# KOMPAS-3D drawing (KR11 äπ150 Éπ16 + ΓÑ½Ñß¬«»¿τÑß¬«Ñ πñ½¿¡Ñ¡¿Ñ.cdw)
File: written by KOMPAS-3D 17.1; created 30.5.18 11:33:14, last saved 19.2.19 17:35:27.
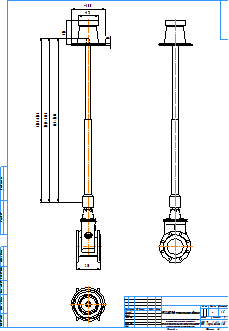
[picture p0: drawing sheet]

Sheet 1: A2, portrait

Title block, sheet 1: name: KR11 Ду150 Ру16 + телескопическое удлинение; sheets: 1; sheet format: A2; stored path: C:\Users\kka\KOMPAS_Work\!Trash\ГРАНАР KR Задвижки с приводами и удлинениями\С удлинениями\KR11 Ду150 Ру16 + телескопическое удлинение.cdw

Views: Вид 1, Проекционный вид 2, Проекционный вид 3
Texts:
  kka
  adl
  Рама для чертежей
  Лит-Масса-Масштаб
  Материал-Предприятие
  Масштаб
  Изм.
  Лист
  № докум.
  Подп.
  Дата
  Лит.
  Разраб.
  Пров.
  Т.контр.
  Листов
  Внимание! Данный продукт является объектом авторского права ООО «Торговый Дом АДЛ».
  Запрещается изменение, копирование, распространение
  (в том числе путем копирования на другие сайты и ресурсы в Интернете)
  или любое иное использование информации и объектов без предварительного
  согласия правообладателя (ООО «Торговый Дом АДЛ»).
  Н.контр.
  Утв.
  ООО "Торговый дом АДЛ"
  Изменение
  Номер документа
  Подпись
  Обозначение документа
  Наименование изделия
  Масса изделия по ГОСТ 2.109-73
  Порядковый номер листа
  Общее количество листов в документе
  Характер работы, выполненной лицом, подписавшим документ
  Наименование или индекс предприятия, выпускающего документ
  Инв. № подл.
  Подп. и дата
  Взам. инв. №
  Инв. № дубл.
  Инвентарный номер подлинника по ГОСТ 2.501-68
  Подпись принявшего подлинник в отдел технической документации
  Инвентарный номер подлинника, взамен которого выпущен данный подлинник
  Инвентарный номер дубликата по ГОСТ 2.502-68
  Подпись принявшего дубликат в отдел технической документации
  Справ. №
  Перв. примен.
  Обозначение документа, взамен или на основании которого выпущен данный документ
  Обозначение документа, в котором впервые записан данный документ
  Подпись лица, копировавшего чертеж
  Обозначение формата листа
  !Рама для чертежа
Dimensions and other numbers on the sheet: 846-; 1465; 1547-2865; 2160-3160; 300; 18; 210; 175; 1:5; 1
